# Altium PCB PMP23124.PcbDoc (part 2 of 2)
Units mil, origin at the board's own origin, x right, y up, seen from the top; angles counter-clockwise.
Board outline 2625 x 1500 mil, 2 copper layers (Top Layer, Bottom Layer), stack 62 mil thick; 59 components, 31 nets, 143 pads, 28 vias.
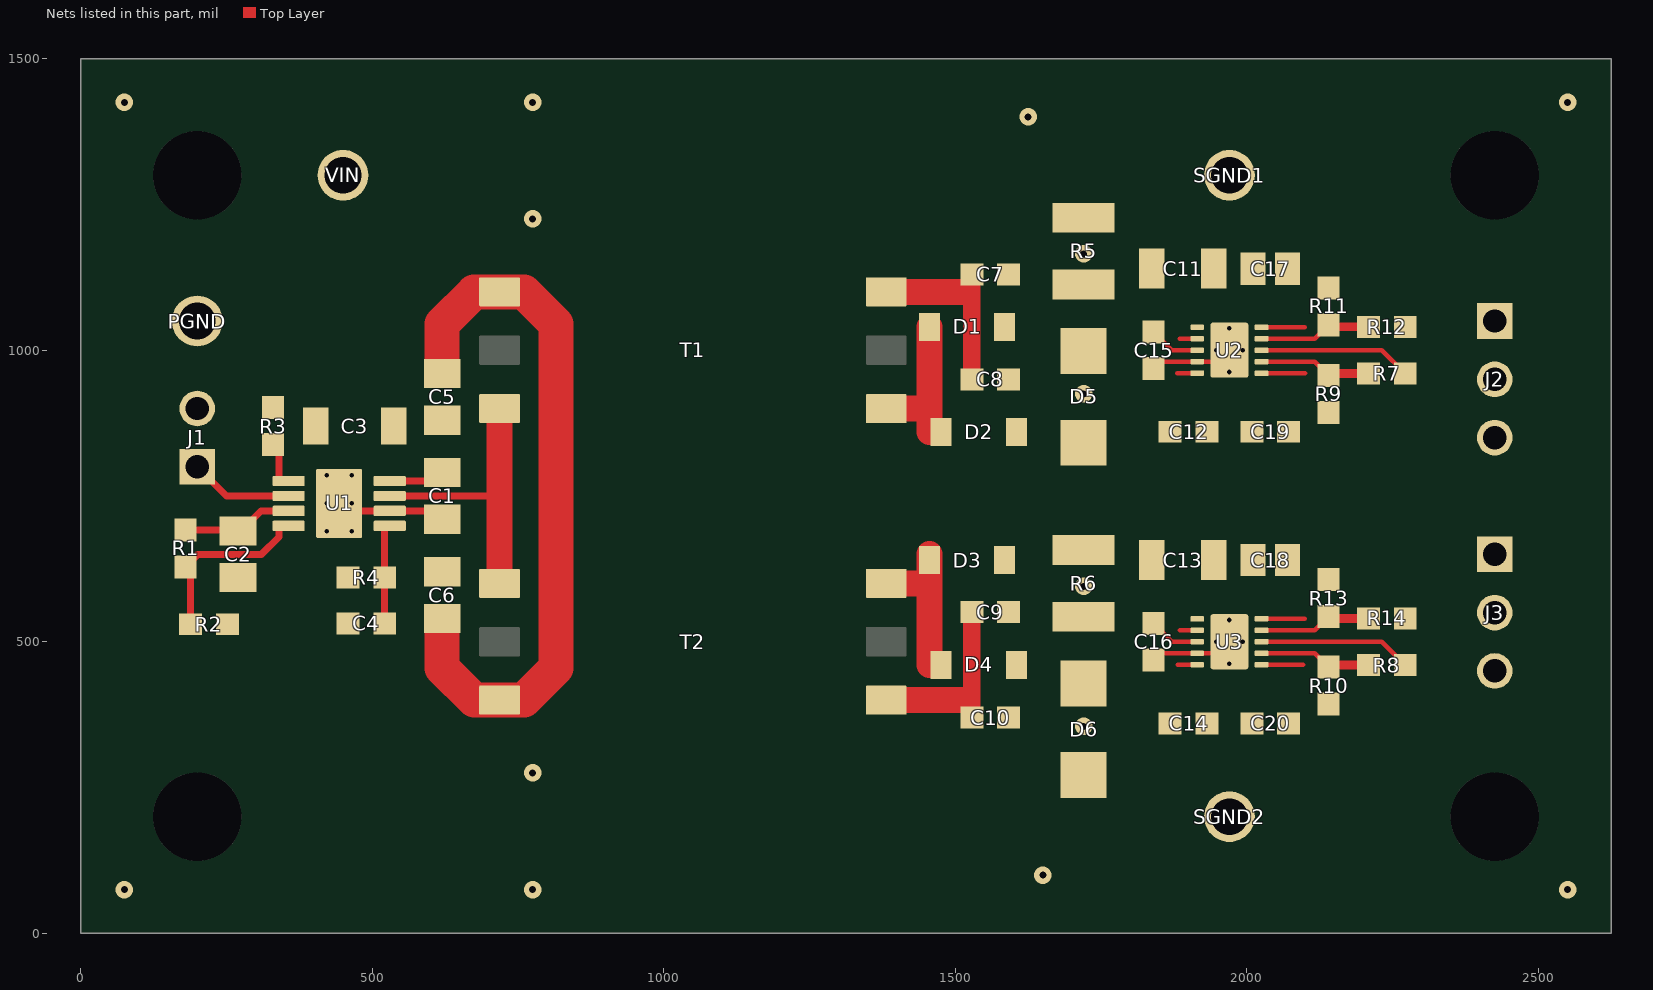
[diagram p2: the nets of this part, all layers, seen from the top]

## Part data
C1 C2 C5 C6: library part CMP-0085980-1, "CAP, CERM, 1 µF, 35 V,+/- 10%, X7R, 0805", Cap_Case=0805, Manufacturer=MuRata, TempCo=X7R, Tolerance_%=10%, Value2=35V, ValueDisplayed=1µF
C3 C11 C13: library part CMP-0008969-2, "CAP, CERM, 4.7 uF, 50 V, +/- 10%, X7R, 1206", Cap_Case=2220, Manufacturer=MuRata, Supplier Part Number 1=24R6347, TempCo=X7R, Tolerance_%=10%, Value1=Unknown, Value2=50V, ValueDisplayed=4.7uF
C4: library part CMP-0007171-4, "CAP, CERM, 100 pF, 50 V, +/- 5%, C0G/NP0, 0603", Cap_Case=0603, Manufacturer=MuRata, Supplier Part Number 1=490-1427-1-ND, TempCo=C0G/NP0, Tolerance_%=5%, Value1=Unknown, Value2=50V, ValueDisplayed=100pF
C7 C8 C9 C10: library part CMP-0007444-5, "CAP, CERM, 0.022 uF, 50 V, +/- 10%, X7R, 0603", Cap_Case=0603, Manufacturer=MuRata, Supplier Part Number 1=490-1517-1-ND, TempCo=X7R, Tolerance_%=10%, Value1=Unknown, Value2=50V, ValueDisplayed=0.022uF
C12 C14: library part CMP-0064936-4, "CAP, CERM, 4.7 uF, 16 V,+/- 10%, X7R, 0603", Cap_Case=0603, Manufacturer=MuRata, TempCo=X7R, Tolerance_%=10%, Value1=Unknown, Value2=16V, ValueDisplayed=4.7uF
C15 C16: library part CMP-0007377-4, "CAP, CERM, 0.01 uF, 16 V, +/- 10%, X7R, 0603", Cap_Case=0603, Manufacturer=MuRata, Supplier Part Number 1=490-1525-1-ND, TempCo=X7R, Tolerance_%=10%, Value1=Unknown, Value2=16V, ValueDisplayed=0.01uF
C17 C18: library part CMP-0008378-2, "CAP, CERM, 10 uF, 25 V, +/- 10%, X7R, 0805", Cap_Case=0805, Manufacturer=MuRata, Supplier Part Number 1=81-GRM21BZ71E106KE5L, TempCo=X7R, Tolerance_%=10%, Value1=Unknown, Value2=25V, ValueDisplayed=10uF
C19 C20: library part CMP-0007497-5, "CAP, CERM, 10 uF, 10 V, +/- 20%, X7R, 0603", Cap_Case=0603, Manufacturer=MuRata, Supplier Part Number 1=81-GRM188Z71A106MA3D, TempCo=X7R, Tolerance_%=20%, Value1=Unknown, Value2=10V, ValueDisplayed=10uF
D1 D2 D3 D4: library part CMP-0079239-2, "Diode, Schottky, 60 V, 1 A, AEC-Q101, SOD-123", Manufacturer=Nexperia, Value1=1A, Value2=0.66V
D5 D6: library part CMP-0005529-3, "Diode, Zener, 5.1 V, 1 W, SMA", Manufacturer="Diodes Inc.", Power_W=1W
H1 H2 H3 H4: library part CMP-0003690-1, Manufacturer=Keystone, Supplier Part Number 1=36-4824-ND
J1: library part CMP-0055333-1, "Header, 2.54mm, 2x1, Tin, TH", Color=Black, Current_A=4A, Manufacturer=Molex, Supplier Part Number 1=WM50016-02-ND, Voltage_V=250V
J2 J3: library part CMP-0055332-1, "Header, 2.54mm, 3x1, Tin, TH", Color=Black, Current_A=4A, Manufacturer=Molex, Supplier Part Number 1=WM50016-03-ND, Voltage_V=250V
Logo1: library part CMP-0074836-1, "IEC 61010-1 Caution Warning", PartNumber="CAUTION.  READ USER GUIDE BEFORE USE"
Logo2: library part CMP-0074769-1
Logo3: library part CMP-0074847-1, "FCC_disclaimer"
PGND SGND1 SGND2: library part CMP-0055148-1, "Test Point, Multipurpose, Black, TH", Color=Black, Manufacturer=Keystone, Supplier Part Number 1=36-5011-ND
R1: library part CMP-0022374-4, "RES, 3.24 k, 1%, 0.1 W, AEC-Q200 Grade 0, 0603", Manufacturer=Vishay-Dale, Power_W=100mW, Supplier Part Number 1=541-3.24KHCT-ND, TempCo="100 ppm/C", Tolerance_%=1%, Value2=0.1W, Value_Code=3k24, ValueDisplayed=3.24k
R2: library part CMP-0022016-4, "RES, 11.0 k, 1%, 0.1 W, AEC-Q200 Grade 0, 0603", Manufacturer=Vishay-Dale, Power_W=100mW, Supplier Part Number 1=541-11.0KHCT-ND, TempCo="100 ppm/C", Tolerance_%=1%, Value2=0.1W, Value_Code=11k0, ValueDisplayed=11.0k
R3 R7 R8 R12 R14: library part CMP-0021998-4, "RES, 10.0 k, 1%, 0.1 W, AEC-Q200 Grade 0, 0603", Manufacturer=Vishay-Dale, Power_W=100mW, Supplier Part Number 1=541-10.0KHCT-ND, TempCo="100 ppm/C", Tolerance_%=1%, Value2=0.1W, Value_Code=10k0, ValueDisplayed=10.0k
R4: library part CMP-0022532-4, "RES, 60.4 k, 1%, 0.1 W, AEC-Q200 Grade 0, 0603", Manufacturer=Vishay-Dale, Power_W=100mW, Supplier Part Number 1=541-60.4KHCT-ND, TempCo="100 ppm/C", Tolerance_%=1%, Value2=0.1W, Value_Code=60k4, ValueDisplayed=60.4k
R5 R6: library part CMP-0083561-1, "RES, 4.7 k, 5%, 0.5 W, 1210", Manufacturer=Yageo, Power_W=500mW, TempCo="100 ppm/C", Tolerance_%=5%, Value2=0.5W, Value_Code=4k70, ValueDisplayed=4.7k
R9 R10: library part CMP-0022346-4, "RES, 34.0 k, 1%, 0.1 W, AEC-Q200 Grade 0, 0603", Manufacturer=Vishay-Dale, Power_W=100mW, Supplier Part Number 1=541-34.0KHCT-ND, TempCo="100 ppm/C", Tolerance_%=1%, Value2=0.1W, Value_Code=34k0, ValueDisplayed=34.0k
R11 R13: library part CMP-0022012-4, "RES, 115 k, 1%, 0.1 W, AEC-Q200 Grade 0, 0603", Manufacturer=Vishay-Dale, Power_W=100mW, Supplier Part Number 1=541-115KHCT-ND, TempCo="100 ppm/C", Tolerance_%=1%, Value2=0.1W, Value_Code=115k
T1 T2: library part CMP-0092417-1, "3:5 OPEN LOOP LLC FOR PMP22930", Manufacturer="Renco Electronics", Operating Temperature Range=to, ValueDisplayed=2.5pF, Voltage_Isolation_Vrms=3kV
U1: library part CMP-0088494-2, "Open Loop LLC Transformer Driver for Isolated Bias Supplies", Manufacturer="Texas Instruments", Max Supply Voltage=36V, Min Supply Voltage=12V, Nominal Supply Current=500uA, Operating Temperature Range="-40°C to +150°C", Switching Frequency=100-2000kHz
U2 U3: library part CMP-0013435-7, "Dual, 150mA, Wide-Vin, Positive and Negative Low-Dropout (LDO) Voltage Regulator, DSC0010J (WSON-10)", Alternate Manufacturer="Texas Instruments", Alternate PartNumber=TPS7A3901DSCT, Operating Temperature Range="-40 to 125 C", Rating=Catalog
VIN: library part CMP-0055147-1, "Test Point, Multipurpose, Red, TH", Color=Red, Manufacturer=Keystone, Supplier Part Number 1=36-5010-ND

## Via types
v1: diameter 19.68, hole 7.87, Top Layer to Bottom Layer, 14 vias
v2: diameter 30, hole 12, Top Layer to Bottom Layer, tented top, 10 vias
v3: diameter 30, hole 12, Top Layer to Bottom Layer, 4 vias

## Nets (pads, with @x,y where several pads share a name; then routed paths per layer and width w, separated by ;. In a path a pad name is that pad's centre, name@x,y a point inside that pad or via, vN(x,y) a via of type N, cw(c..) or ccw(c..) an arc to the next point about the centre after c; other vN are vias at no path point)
+15V: C1.1 C3.1 C5.1 U1.8 VIN.1 | length 96
  Top Layer w12: U1.8@530,775.59 605.59,775.59 C1.1@620,790
NetC2_1: C2.1 R1.2 U1.3 | length 191.6
  Top Layer w12: R1.2@180,691.5 268.5,691.5 C2.1@270,690 275,690 309.41,724.41 U1.3@356.77,724.41
NetC4_1: C4.1 R4.2 U1.5 | length 175.8
  Top Layer w12: C4.1@521.5,531.49 521.5,698.82 U1.5@530,698.82
NetC5_2: C5.2 C6.1 T1.1 T2.3 | length 1221.1
  Top Layer w60: C6.1@620,530 620,455 675,400 T2.3@718.5,400 760,400 815,455 815,1045 760,1100 T1.1@718.5,1100 675,1100 620,1045 C5.2@620,970
NetC7_1: C7.1 C8.2 T1.6 | length 318.5
  Top Layer w30: C8.2@1528.5,950 C7.1@1528.5,1130
  Top Layer w45: T1.6@1381.5,1100 1520,1100
NetC7_2: C7.2 C11.1 D1.1 R5.2 U2.1 U2.2 | length 30
  Top Layer w8: 1884.88,1019.68 U2.2@1914.88,1019.68
NetC8_1: C8.1 C12.2 D2.2 D5.2 U2.5 | length 34.3
  Top Layer w8: 1880.63,960.63 U2.5@1914.88,960.63
NetC9_1: C9.1 C10.2 T2.4 | length 319.4
  Top Layer w30: C10.2@1528.5,370 C9.1@1528.5,550.89
  Top Layer w45: T2.4@1381.5,400 1520,400
NetC9_2: C9.2 C13.1 D3.1 R6.2 U3.1 U3.2 | length 29.7
  Top Layer w8: 1885.19,519.68 U3.2@1914.88,519.68
NetC10_1: C10.1 C14.2 D4.2 D6.2 U3.5 | length 33.6
  Top Layer w8: 1881.26,460.63 U3.5@1914.88,460.63
NetC15_1: C15.1 U2.3 | length 87.9
  Top Layer w8: C15.1@1840,1031.49 1871.49,1000 U2.3@1914.88,1000
NetC16_1: C16.1 U3.3 | length 87.9
  Top Layer w8: C16.1@1840,531.49 1871.49,500 U3.3@1914.88,500
NetC17_1: C17.1 J2.1 R11.2 U2.10 | length 73.9
  Top Layer w8: U2.10@2025.11,1039.37 2098.99,1039.37
NetC18_1: C18.1 J3.1 R13.2 U3.10 | length 73.9
  Top Layer w8: U3.10@2025.11,539.37 2098.99,539.37
NetC19_1: C19.1 J2.3 R9.1 U2.6 | length 74.5
  Top Layer w8: U2.6@2025.11,960.63 2099.63,960.63
NetC20_1: C20.1 J3.3 R10.1 U3.6 | length 71.1
  Top Layer w8: U3.6@2025.11,460.63 2096.25,460.63
NetD1_2: D1.2 D2.1 T1.4 | length 238.5
  Top Layer w45: T1.4@1381.5,900 1435.53,900 ; D1.2@1455.53,1040 1455.53,860 D2.1@1460,860
NetD3_2: D3.2 D4.1 T2.6 | length 267.6
  Top Layer w45: T2.6@1381.5,600 1455.53,600 ; D3.2@1455.53,650 D3.2@1455.53,640 1455.53,600 ; D4.1@1459.58,460.42 1455.53,460.42 1455.53,600
NetJ1_1: J1.1 U1.2 | length 177.5
  Top Layer w12: J1.1@200,800 249.99,750 U1.2@356.77,750
NetR1_1: R1.1 R2.2 U1.4 | length 318.9
  Top Layer w12: R2.2@188.5,530 188.5,620 R1.1@180,628.5 201.5,650 310,650 340,680 340,698.82 U1.4@356.77,698.82
NetR3_2: R3.2 U1.1 | length 83.8
  Top Layer w12: R3.2@330,838.5 340,828.5 340,775.59 U1.1@356.77,775.59
NetR7_1: R7.1 R9.2 U2.7 | length 194.7
  Top Layer w8: U2.7@2025.11,980.31 2116.18,980.31 R9.2@2140,956.49
  Top Layer w15: R9.2@2140,956.49 2143.5,960 R7.1@2208.5,960
NetR7_2: R7.2 U2.8 | length 262.9
  Top Layer w8: U2.8@2025.11,1000 2231.49,1000 R7.2@2271.49,960
NetR8_1: R8.1 R10.2 U3.7 | length 194.7
  Top Layer w8: U3.7@2025.11,480.31 2116.18,480.31 R10.2@2140,456.49
  Top Layer w15: R10.2@2140,456.49 2143.5,460 R8.1@2208.5,460
NetR8_2: R8.2 U3.8 | length 262.9
  Top Layer w8: U3.8@2025.11,500 2231.49,500 R8.2@2271.49,460
NetR11_1: R11.1 R12.1 U2.9 | length 194.7
  Top Layer w8: U2.9@2025.11,1019.68 2116.18,1019.68 R11.1@2140,1043.5
  Top Layer w15: R11.1@2140,1043.5 2143.5,1040 R12.1@2208.5,1040
NetR13_1: R13.1 R14.1 U3.9 | length 194.7
  Top Layer w8: U3.9@2025.11,519.68 2116.18,519.68 R13.1@2140,543.5
  Top Layer w15: R13.1@2140,543.5 2143.5,540 R14.1@2208.5,540
NetT1_3: T1.3 T2.1 U1.7 | length 488.5
  Top Layer w12: U1.7@530,750 718.5,750
  Top Layer w45: T2.1@718.5,600 718.5,750 T1.3@718.5,900
PGND: C1.2 C2.2 C3.2 C4.2 C6.2 J1.2 PGND.1 R2.1 R3.1 R4.1 U1.6 U1.9 | length 187.9
  Top Layer w12: U1.9@443.39,737.2 456.18,724.41 U1.6@530,724.41 605.59,724.41 C1.2@620,710
  other v1: 421.73,689.17 465.04,689.17 421.73,737.2 465.04,737.2 421.73,785.24 465.04,785.24
  other v2: 75,75 775,75 775,275 775,1225 75,1425 775,1425
SGND1: C11.2 C12.1 C15.2 C17.2 C19.2 D5.1 J2.2 R5.1 R12.2 SGND1.1 U2.4 U2.11 | length 143.1
  Top Layer w8: C15.2@1840,968.5 1851.81,980.31 U2.4@1914.88,980.31 1950.31,980.31 U2.11@1970,1000
  other v1: 1970,962.6 1947.36,1000 1992.63,1000 1970,1037.4
  other v2: 1625,1400 2550,1425
  other v3: 1720,925 1720,1165
SGND2: C13.2 C14.1 C16.2 C18.2 C20.2 D6.1 J3.2 R6.1 R14.2 SGND2.1 U3.4 U3.11 | length 143.1
  Top Layer w8: C16.2@1840,468.5 1851.81,480.31 U3.4@1914.88,480.31 1950.31,480.31 U3.11@1970,500
  other v1: 1970,462.6 1947.36,500 1992.63,500 1970,537.4
  other v2: 2550,75 1650,100
  other v3: 1720,355 1720,595
pads on no net: H1.0 H1.MH H2.0 H2.MH H3.0 H3.MH H4.0 H4.MH T1.2 T1.5 T2.2 T2.5

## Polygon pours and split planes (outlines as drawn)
SGND2 on Top Layer "Top Layer-No Net 6" (solid, remove dead copper, pour order 26): 1565,700 1565,0 2625,0 2625,700
SGND1 on Top Layer "Top Layer-No Net 6" (solid, remove dead copper, pour order 22): 1565,800 1565,1500 2625,1500 2625,800
NetC8_1 on Top Layer "Top Layer-No Net 6" (solid, remove dead copper, pour order 20): 1640,1085 1640,940 1695,885 1745,885 1793.92,933.92 1870,933.92 1870,1075 1930,1075 1930,928.5 1895,893.5 1895,800 1565,800 1565,1085
NetC10_1 on Top Layer "Top Layer-No Net 6" (solid, remove dead copper, pour order 18): 1640,515 1640,370 1695,315 1745,315 1800,370 1800,433.92 1870,433.92 1870,505 1930,505 1930,430 1895,395 1895,200 1565,200 1565,515
NetC9_2 on Top Layer "Top Layer-No Net 6" (solid, remove dead copper, pour order 16): 1640,519.68 1640,575 1695,630 1745,630 1800,575 1800,566.35 1870,566.35 1870,440 1930,440 1930,565 1890,605 1890,700 1565,700 1565,519.68
NetC7_2 on Top Layer "Top Layer-No Net 6" (solid, remove dead copper, pour order 14): 1640,1000 1640,1145 1695,1200 1745,1200 1800,1145 1800,1066.35 1870,1066.35 1870,1010 1930,1010 1930,1065 1890,1105 1890,1300 1565,1300 1565,1000
NetC17_1 on Top Layer "Top Layer-No Net 6" (solid, remove dead copper, pour order 12): 2010,1035 2354.74,1035 2389.74,1000 2460,1000 2460,1265 2425,1300 2050,1300 2050,1100 2010,1060
NetC19_1 on Top Layer "Top Layer-No Net 6" (solid, remove dead copper, pour order 10): 2010,965 2265,965 2330,900 2460,900 2460,800 2050,800 2050,890 2010,930
NetC20_1 on Top Layer "Top Layer-No Net 6" (solid, remove dead copper, pour order 8): 2010,465 2305,465 2305,500 2460,500 2460,200 2045,200 2045,395 2010,430
NetC18_1 on Top Layer "Top Layer-No Net 6" (solid, remove dead copper, pour order 6): 2010,530 2206.31,530 2276.31,600 2460,600 2460,700 2050,700 2050,600 2010,560
PGND on Top Layer "Top Layer-No Net 6" (solid, remove dead copper, pour order 2): 0,1500 850,1500 850,1145 720,1145 660,1085 660,415 720,355 850,355 850,0 0,0
+15V on Top Layer "Top Layer-No Net 6" (solid, remove dead copper, pour order 0): 375,1375 525,1375 525,1255 660,1120 660,760 500.08,760 500.08,899.91 375,1024.99
SGND2 on Bottom Layer "Top Layer-No Net 6" (solid, remove dead copper, pour order 30): 1350,700 1350,0 2625,0 2625,700
SGND1 on Bottom Layer "Top Layer-No Net 6" (solid, remove dead copper, pour order 24): 1350,800 1350,1500 2625,1500 2625,800
PGND on Bottom Layer "Top Layer-No Net 6" (solid, remove dead copper, pour order 4): 0,1500 850,1500 850,0 0,0

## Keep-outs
Keep-Out Layer:
  text ".Layer_Name" at 577,-858.49 h60

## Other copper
Top Layer:
  pour cut-out: 2173.7,1078.19 2311.55,1078.19 2362.27,1027.46 2352.99,1018.18 2297.99,1073.19 2173.82,1073.7
  text ".Layer_Name" at 577,-858.49 h60
Bottom Layer:
  text ".Layer_Name" at 577,-858.49 h60

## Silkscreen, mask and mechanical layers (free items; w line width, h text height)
Top Overlay:
  text "PMP23124A" at 800,1350 h120
  text "+15V" at 2500,1030 h50
  text "GND" at 2500,930 h50
  text "-4V" at 2500,830 h50
  text "+15V" at 2500,630 h50
  text "GND" at 2500,530 h50
  text "-4V" at 2500,430 h50
  text ".Layer_Name" at 577,-858.49 h60
Bottom Overlay:
  text ".Layer_Name" at 577,-858.49 h60
Top Paste:
  text ".Layer_Name" at 577,-858.49 h60
Bottom Paste:
  text ".Layer_Name" at 577,-858.49 h60
Top Solder:
  text ".Layer_Name" at 577,-858.49 h60
  text ".Layer_Name" at 577,-858.49 h60
Bottom Solder:
  text ".Layer_Name" at 577,-858.49 h60
Drill Guide:
  text ".Layer_Name" at 577,-858.49 h60
M1 Board Outline:
  the board outline again, w10
  text ".Layer_Name" at 577,-858.49 h60
M2 Board Dimensions:
  rectangle: 0,-275 125,-150
  rectangle: 125,-400 500,-275
  lines w7: 0,-275 1000,-275 ; 125,-400 125,-150 ; 250,-400 250,-150 ; 500,-400 500,-150 ; 750,-400 750,-150 ; 0,-400 1000,-400 1000,-150 0,-150 0,-400
  text ".Layer_Name" at 577,-858.49 h60
M3 3D STEP Top:
  text ".Layer_Name" at 577,-858.49 h60
M4 3D STEP Bottom:
  text ".Layer_Name" at 577,-858.49 h60
M5 Assembly Top:
  lines w10: -292,-930.17 6308,-930.17 ; -292,-726.83 6310,-726.83 ; -292,-523.5 -292,-1133.5 3713,-1133.5 6310,-1133.5 6310,-523.5 -291.5,-523.5 -291.5,-1133.5 1284,-1133.5 ; 2173,-1133.5 2173,-523.5 ; 3440,-726.83 3440,-523.5 ; 4280,-726.83 4280,-523.5 ; 4902,-1140 4902,-937.17
  text "COMPONENTS MARKED 'DNP' SHOULD NOT BE POPULATED." at 1153.5,-318.5 h60
  text "ASSEMBLY VARIANT:" at 1153,-434 h60
  text ".VariantName" at 2189,-434 h60
  text "PCB VIEWED FROM TOP SIDE" at -228.5,-655.67 h60
  text "BOARD #:" at 2248,-655.67 h60
  text ".PRJ_Number" at 2793.5,-655.67 h60
  text "REV:" at 3638,-655.67 h60
  text ".PCB_Rev" at 3929.5,-655.67 h60
  text "SVN REV:" at 4476,-655.67 h60
  text ".VersionControl_RevNumber" at 4982,-655.67 h60
  text "TID #:" at 2248,-859 h60
  text ".TID" at 2793.5,-859 h60
  text "PLOT NAME =" at -228.5,-1064.34 h60
  text ".plot_File_Name" at 577,-1064.34 h60
  text "GENERATED    :" at 2250,-1064.34 h60
  text ".Print_Date" at 3119.5,-1064.34 h60
  text ".Print_Time" at 3848.5,-1064.34 h60
  text "TEXAS INSTRUMENTS" at 5113,-1064.34 h60
M6 Assembly Bottom:
  lines w10: -292.5,-727.33 6309.5,-727.33 ; -290.5,-930.67 6309.5,-930.67 ; 1115.5,-1140.5 1115.5,-937.67 ; 1737.5,-727.33 1737.5,-524 ; 2577.5,-727.33 2577.5,-524 ; 3844.5,-1134 3844.5,-524 ; 4733.5,-1134 6309,-1134 6309,-524 -292.5,-524 -292.5,-1134 2304.5,-1134 6309.5,-1134 6309.5,-524
  text "COMPONENTS MARKED 'DNP' SHOULD NOT BE POPULATED." at 6102,-318 h60
  text ".VariantName" at 5058,-434 h60
  text "ASSEMBLY VARIANT:" at 6097,-434 h60
  text ".VersionControl_RevNumber" at 1035.5,-656.17 h60
  text "SVN REV:" at 1541.5,-656.17 h60
  text ".PCB_Rev" at 2088,-656.17 h60
  text "REV:" at 2379.5,-656.17 h60
  text ".PRJ_Number" at 3224,-656.17 h60
  text "BOARD #:" at 3769.5,-656.17 h60
  text "PCB VIEWED FROM BOTTOM SIDE" at 6246,-656.17 h60
  text ".TID" at 3224,-859.5 h60
  text "TID #:" at 3769.5,-859.5 h60
  text "TEXAS INSTRUMENTS" at 904.5,-1064.84 h60
  text ".Print_Time" at 2169,-1064.84 h60
  text ".Print_Date" at 2898,-1064.84 h60
  text "GENERATED    :" at 3767.5,-1064.84 h60
  text ".plot_File_Name" at 5440.5,-1064.84 h60
  text "PLOT NAME =" at 6246,-1064.84 h60
M9 Title Sheet:
  drawing of 57 lines, arcs and shapes, not listed
  text "1" at 739.84,8036.5 h70
  text "2" at 3235.5,8036.5 h70
  text "3" at 5724.84,8036.5 h70
  text "4" at 8231.51,8036.5 h70
  text "5" at 10730.5,8036.5 h70
  text "6" at 13235.5,8036.5 h70
  text "A" at -416.5,6893.5 h70
  text "A" at 14383.5,6893.5 h70
  text "B" at -416.5,4513.5 h70
  text "B" at 14383.5,4513.5 h70
  text "C" at -416.5,2138.5 h70
  text "C" at 14383.5,2138.5 h70
  text "PROJECT TITLE:" at 11343.5,277.5 h45
  text ".PRJ_Title" at 11393.5,144.17 h70
  text "DESIGNED FOR:" at 11343.5,-23.5 h45
  text ".PRJ_Customer" at 11393.5,-163.5 h70
  text "D" at -416.5,-231.5 h70
  text "D" at 14383.5,-231.5 h70
  text "FILE NAME:" at 11343.5,-323.5 h45
  text ".PCB_File_Name_No_Path" at 11393.5,-443.5 h70
  text "Texas Instruments (TI) and/or its licensors do not warrant the accuracy or completeness of this specification" at 6374,-605.34 h45
  text "ENGINEER:" at 11343.5,-613.5 h45
  text "LAYOUT BY:" at 12848.5,-613.5 h45
  text "or any information contained therein. TI and/or its licensors do not warrant that this design will meet" at 6329.01,-718 h45
  text ".PRJ_Engineer" at 11393.5,-768.49 h70
  text ".PCB_Layout" at 12899,-768.49 h70
  text "the specifications, will be suitable for your application or fit for any particular purpose, or will operate in" at 6329.01,-830.67 h45
  text ".Layer_Name" at 577,-858.49 h60
  text "ALTIUM DESIGNER VERSION:" at 12848.5,-923.5 h45
  text "an implementation. TI and/or its licensors do not warrant that the design is production worthy. You should" at 6329.01,-943.33 h45
  text "completely validate and test your design implementation to confirm the system functionality for your application." at 6374,-1056 h45
  text ".print_Scale" at 11393.5,-1056.83 h70
  text ".Application_BuildNumber" at 12899,-1056.83 h70
  text "1" at 739.84,-1263.5 h70
  text "2" at 3235.5,-1263.5 h70
  text "3" at 5724.84,-1263.5 h70
  text "4" at 8231.51,-1263.5 h70
  text "5" at 10730.5,-1263.5 h70
  text "6" at 13235.5,-1263.5 h70
M10 Fab Notes:
  drawing of 189 lines, arcs and shapes, not listed
  text "DESIGN INFORMATION" at 12382.02,6356.17 h60
  text "MIN. TRACK WIDTH:" at 11737.46,6224.05 h60
  text "8" at 12833.7,6224.05 h60
  text "MIL" at 12988.46,6224.05 h60
  text "7.874" at 12667.32,6102.36 h60
  text "MIN. CLEARANCE:" at 11737.46,6099.92 h60
  text "MIL" at 12988.46,6099.92 h60
  text "MIN. VIA PAD SIZE:" at 11737.46,5975.8 h60
  text "24" at 12803.71,5975.8 h60
  text "MIL" at 12988.46,5975.8 h60
  text "0.05mm (2MIL)" at 12432.46,5845.9 h60
  text "MINIMUM ANNULAR RING" at 11408.23,5837.67 h60
  text "EXTERNAL" at 13140.46,5837.67 h60
  text "PER" at 11608.23,5727.55 h60
  text "IPC-D-275 CLASS 2 LEVEL C" at 11828.23,5727.54 h60
  text "MIL, HOLES" at 13316.46,5627.07 h60
  text "+/-" at 12924,5618.48 h60
  text "+/-" at 13778,5618.48 h60
  text "REGISTRATION TOLERANCES:" at 11408.23,5617.42 h60
  text "METAL" at 12608,5617.42 h60
  text "5" at 13184.2,5617.42 h60
  text "3" at 14017.2,5617.42 h60
  text "MIL" at 14133.46,5617.42 h60
  text "HOLE SIZE TOLERANCE (UNLESS OTHERWISE SPECIFIED):" at 11408.23,5519.1 h60
  text "+/-" at 13778,5516.23 h60
  text "3" at 14017.2,5515.17 h60
  text "MIL" at 14133.46,5515.17 h60
  text "MATERIAL:" at 11333.46,5377.52 h60
  text "FR-4 High Tg" at 12319.9,5249 h60
  text "X" at 12175.46,5241.01 h60
  text "FR-408" at 11754.46,5236.49 h60
  text "OTHER" at 13242.46,5236.49 h60
  text "62 MIL (1.6mm) +/-10%" at 12074.56,5093.46 h60
  text "X" at 11954.46,5091.01 h60
  text "THICKNESS:" at 11408.23,5085.24 h60
  text "OTHER" at 13359.46,5085.24 h60
  text "TOLERANCE:" at 11408.23,4946.92 h60
  text "X" at 12256.46,4946.92 h60
  text "ANSI IPC-6012 TYPE 3 CLASS 2" at 12434.48,4946.92 h60
  text "OTHER +/-" at 12434.46,4802.73 h60
  text "BOW & TWIST:" at 11408.23,4657.54 h60
  text "X" at 12256.46,4657.54 h60
  text "ANSI IPC-6012 TYPE 3 CLASS 2" at 12434.48,4657.54 h60
  text "OTHER +/-" at 12434.46,4510.85 h60
  text "DRILLING:" at 11333.46,4380.23 h60
  text "NC_DRILL FILES" at 13094.46,4275.04 h60
  text "REFERENCE:" at 11408.23,4271.1 h60
  text "X" at 12065.46,4271.01 h60
  text "AS SHOWN" at 12243.46,4271.1 h60
  text "X" at 12966.46,4271.1 h60
  text "OTHER" at 13392.46,4128.85 h60
  text "PTH COPPER THICKNESS:" at 11407.91,4125.32 h60
  text "X" at 12547.14,4125.32 h60
  text "20-30 um" at 12675.14,4125.32 h60
  text "BOARD FINISH:" at 11333.46,3977.73 h60
  text "SILKSCREEN:" at 11488.68,3867.6 h60
  text "X" at 12446.46,3867.6 h60
  text "TOP" at 12563.46,3867.6 h60
  text "X" at 12956.46,3867.6 h60
  text "BOTTOM" at 13074.46,3867.6 h60
  text "SILKSCREEN COLOR:" at 11488.68,3712.41 h60
  text "X" at 12445.46,3712.41 h60
  text "WHITE" at 12563.46,3712.41 h60
  text "OTHER" at 13074.46,3712.41 h60
  text "X" at 12576.46,3568.96 h60
  text "GREEN" at 12694.46,3568.96 h60
  text "OTHER" at 13312.46,3568.96 h60
  text "SOLDER RESIST COLOR:" at 11488.68,3562.1 h60
  text "X" at 12576.46,3414.71 h60
  text "MATTE" at 12694.46,3414.71 h60
  text "SEMI-GLOSS" at 13312,3414.07 h60
  text "IMMERSION GOLD (ENIG)" at 12394.46,3241.94 h60
  text "ENEPIG" at 13732,3234.72 h60
  text "SURFACE FINISH:" at 11333.46,3233.72 h60
  text "X" at 12216.46,3233.72 h60
  text "IMM. TIN/SILVER OR EQUIV" at 11663,3096.4 h60
  text "OTHER" at 13094.46,3092.47 h60
  text "ARRAY/PANEL:" at 11333.46,2937.09 h60
  text "CUT AND TRIM PER M1 BOARD OUTLINE" at 12394.46,2928.87 h60
  text "N.C. ROUTE" at 12394.46,2792.9 h60
  text "X" at 13082.46,2792.9 h60
  text "V. SCORE" at 13260.46,2792.9 h60
  text "CERTIFICATION:" at 11333.46,2663.77 h60
  text "MATERIALS AND WORKMANSHIP FOR ALL PCBS" at 12058.46,2663.77 h60
  text "TO MEET OR EXCEED THE REQUIREMENTS OF:" at 12058.46,2569.71 h60
  text "X" at 11695.97,2441.08 h60
  text "ANSI IPC-A-600F CLASS ->" at 11823.96,2441.08 h60
  text "X" at 13471.97,2441.08 h60
  text "2" at 13581.96,2441.08 h60
  text "1" at 13266.96,2439.58 h60
  text "3" at 13935.96,2439.58 h60
  text "X" at 12507.97,2293.39 h60
  text "RoHS" at 12635.96,2293.39 h60
  text "OTHER" at 13280.36,2293.39 h60
  text "PER ORDER" at 13677.42,2293.39 h60
  text "ALL BOARDS MUST MEET OR EXCEED UL94-V0 REQUIREMENTS." at 11361,2139.57 h60
  text "PCB MUST BEAR THE UL94V-0 UL REGISTERED MATERIAL ID NUMBER" at 11361,2023.5 h60
  text "ADDITIONAL REQUIREMENTS:" at 11333.46,1854.08 h60
  text "MICROSECTION:" at 11408.23,1746.95 h60
  text "YES" at 12313.96,1746.95 h60
  text "REQUIRED" at 13175.46,1602.62 h60
  text "BARE BOARD ELEC. TEST:" at 11408.23,1599.76 h60
  text "NONE" at 12713.96,1599.76 h60
  text "X" at 13057.46,1599.76 h60
  text "PER ORDER" at 13767.46,1599.76 h60
  text "XX MIL VIAS REQUIRE NON-CONDUCTIVE FILL AND PLANARIZE" at 11576.38,1394.82 h59
  text "XX MIL VIAS REQUIRE CONDUCTIVE FILL AND PLANARIZE" at 11584.38,1290.84 h60
  text "OUTER XX MIL TRACES REQUIRE 50 OHM SINGLE-ENDED IMPEDANCE" at 11583.39,1127.46 h58
  text "LAYER 2 & 3 (INNER LAYERS) XX MIL WIDE, XX MIL SPACE / TRACES REQUIRE 100 OHM DIFFERENTIAL IMPEDANCE" at 11575.39,891.74 h60
  text ".Layer_Name" at 577,-858.49 h60
M11 Gerber Information:
  lines w10: -292,-930.17 6308,-930.17 ; -292,-726.83 6310,-726.83 ; -292,-523.5 -292,-1133.5 3713,-1133.5 6310,-1133.5 6310,-523.5 -291.5,-523.5 -291.5,-1133.5 1284,-1133.5 ; 2173,-1133.5 2173,-523.5 ; 3440,-726.83 3440,-523.5 ; 4280,-726.83 4280,-523.5 ; 4902,-1140 4902,-937.17
  text "ALL ARTWORK VIEWED FROM TOP SIDE" at -228.5,-655.67 h60
  text "BOARD #:" at 2248,-655.67 h60
  text ".PRJ_Number" at 2793.5,-655.67 h60
  text "REV:" at 3638,-655.67 h60
  text ".PCB_Rev" at 3929.5,-655.67 h60
  text "SVN REV:" at 4476,-655.67 h60
  text ".VersionControl_RevNumber" at 4982,-655.67 h60
  text "LAYER NAME =" at -228.5,-858.49 h60
  text "TID #:" at 2248,-859 h60
  text ".TID" at 2793.5,-859 h60
  text "PLOT NAME =" at -228.5,-1064.34 h60
  text ".plot_File_Name" at 577,-1064.34 h60
  text "GENERATED    :" at 2250,-1064.34 h60
  text ".Print_Date" at 3119.5,-1064.34 h60
  text ".Print_Time" at 3848.5,-1064.34 h60
  text "TEXAS INSTRUMENTS" at 5113,-1064.34 h60
M12 Stackup:
  drawing of 191 lines, arcs and shapes, not listed
  text "Layer" at 9821.59,7717.44 h60
  text "Name" at 10231.51,7717.44 h60
  text "Material" at 11161.25,7717.44 h60
  text "Thickness" at 12021.02,7717.44 h60
  text "Constant" at 12670.85,7717.44 h60
  text "Board Layer Stack" at 13240.71,7717.44 h60
  text "Top Overlay" at 10231.51,7597.44 h60
  text "Top Solder" at 10231.51,7477.44 h60
  text "Solder Resist" at 11161.25,7477.44 h60
  text "0.40mil" at 12021.02,7477.44 h60
  text "3.5" at 12670.85,7477.44 h60
  text "1" at 9821.59,7357.44 h60
  text "Top Layer" at 10231.51,7357.44 h60
  text "1.40mil" at 12021.02,7357.44 h60
  text "Dielectric1" at 10231.51,7237.44 h60
  text "FR-4 High Tg" at 11161.25,7237.44 h60
  text "59.20mil" at 12021.02,7237.44 h60
  text "4.8" at 12670.85,7237.44 h60
  text "2" at 9821.59,7117.44 h60
  text "Bottom Layer" at 10231.51,7117.44 h60
  text "1.40mil" at 12021.02,7117.44 h60
  text "Bottom Solder" at 10231.51,6997.44 h60
  text "Solder Resist" at 11161.25,6997.44 h60
  text "0.40mil" at 12021.02,6997.44 h60
  text "3.5" at 12670.85,6997.44 h60
  text "Bottom Overlay" at 10231.51,6877.44 h60
  text ".Layer_Name" at 577,-858.49 h60
M13 Component Bodies Top:
  text ".Layer_Name" at 577,-858.49 h60
M14 Component Bodies Bottom:
  text ".Layer_Name" at 577,-858.49 h60
M15 Courtyards Top:
  text ".Layer_Name" at 577,-858.49 h60
M16 Courtyards Bottom:
  text ".Layer_Name" at 577,-858.49 h60
Drill Drawing:
  text ".Layer_Name" at 577,-858.49 h60
M17 Embedded Cavity:
  text ".Layer_Name" at 577,-858.49 h60
M18 Embedded Assembly:
  text ".Layer_Name" at 577,-858.49 h60
M19 Embedded Keepout:
  text ".Layer_Name" at 577,-858.49 h60

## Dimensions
0,-400 to 1000,-400 on M2 Board Dimensions
0,0 to 0,1500 on M2 Board Dimensions
0,0 to 2625,0 on M2 Board Dimensions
